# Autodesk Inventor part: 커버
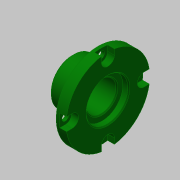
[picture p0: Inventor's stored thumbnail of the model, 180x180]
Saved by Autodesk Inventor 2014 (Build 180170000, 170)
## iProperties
Created: 2019-10
Part Number: 커버
Material: 알루미늄 6061
Document SubType Name: Modeling
Designer: mduedu
Density: 1 g/cm^3
Appearance: Dark Green
Author: mduedu
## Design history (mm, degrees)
sketch "스케치1"
  geometry: L1 (0, 0)-(-18, 0); L2 (-18, 0)-(-18, 11.5); L3 (-18, 11.5)-(-5, 11.5); L4 (-5, 11.5)-(-5, 21); L5 (-5, 21)-(0, 21); L6 (0, 21)-(0, 0)
  constraints: 12 end point, 3 parallel, 2 perpendicular, 1 horizontal
  dimensions: "d0" = 18 distance of L1.start L1.end; "d1" = 42 diameter of L5 L1; "d2" = 23 diameter of L3 L1; "d3" = 13 distance of L2.end L3.end
revolve "회전1" sketch "스케치1" stored, may be unused: angle "d4" = 90 deg
hole "구멍1" diameter "d7" = 15; stored, may be unused: countersink angle "d11" = 90 deg, drill point angle "d13" = 118 deg; dims "d5" = 10, "d6" = 10, "d8" = 6, "d9" = 21, "d10" = 3, "d12" = 8
chamfer "모따기1" distance "d14" = 1; stored, may be unused: second distance "d15" = 2, angle "d16" = 45 deg
sketch "스케치2" dims "d17" = 36
  geometry: 6 further points
  constraints: 2 vertical alignment, 1 coincident, 7 other
  dimensions: "d20" = 360 deg dimension on point (0, 0) point (0, 18) (derived)
sketch "스케치3"
  geometry: 4 further points
  constraints: 4 other
hole "구멍2" sketch "스케치3" at (-18, 0), (0, -18), (18, 0), (0, 18) diameter "d22" = 3.4; stored, may be unused: countersink angle "d26" = 90 deg, drill point angle "d28" = 0 deg; dims "d23" = 6, "d24" = 6.5, "d25" = 3.4, "d27" = 8
sketch "스케치4"
  geometry: L1 (-21.25, 20.747)-(-21.25, 18); L2 (-14.75, 18)-(-14.75, 20.747); A1 r 3.25 centre (-18, 18) between (-19.349, 20.957) and (-16.651, 20.957) reference; A2 r 21 centre (-18, 0) between (-19.349, 20.957) and (-38.957, 1.349) reference; A3 r 21 centre (-18, 0) between (2.957, 1.349) and (-16.651, 20.957) reference; A4 r 21 centre (-18, 0) between (-14.75, 20.747) and (-21.25, 20.747); A5 r 3.25 centre (-18, 18) between (-21.25, 18) and (-14.75, 18); 1 further point
  constraints: 8 point on circle, 4 end point, 2 centre point, 2 coincident, 2 tangent, 1 parallel, 1 vertical
extrude "돌출1" cut sketch "스케치4" stored distance "d29" = 10; taper "d30" = 0 deg
chamfer "모따기3" distance "d37" = 0.5; stored, may be unused: second distance "d38" = 2, angle "d39" = 45 deg
chamfer "모따기4" distance "d40" = 0.5; stored, may be unused: second distance "d41" = 2, angle "d42" = 45 deg
node "솔리드1"
pattern_circular "원형 패턴1" dims angle "d32" = 360 deg
